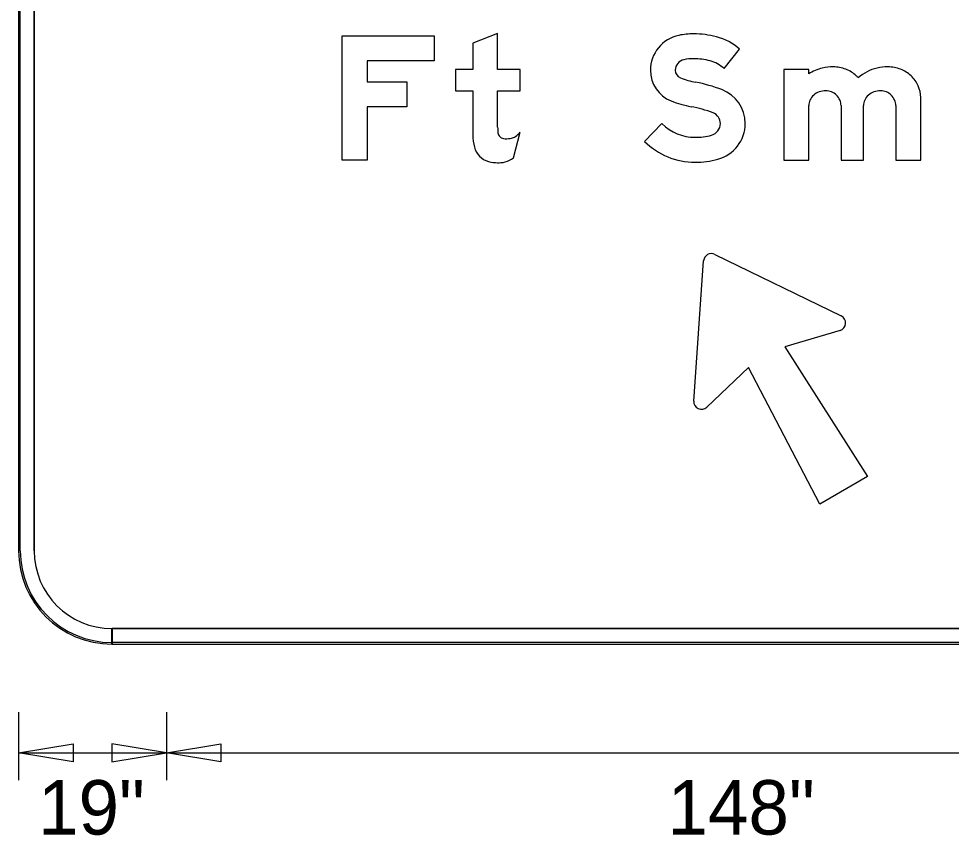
# Model space of a CAD drawing. Extents: x 2150010 to 2150174, y 145114 to 145224.
# Drawn here: x 2150031.52 to 2150041.52, y 145141.83 to 145150.58 of the extents above; entities that cross this region are included whole.
import ezdxf

# ---------------------------------------------------------------- set-up
doc = ezdxf.new("R2010")
doc.units = 0
for name, color, linetype in [('GSBWFILL', 7, 'Continuous'), ('GSCOLORFILL', 7, 'Continuous'), ('GSDIMS', 7, 'Continuous'), ('GSOUTLINE', 7, 'Continuous')]:
    doc.layers.add(name, color=color, linetype=linetype)

msp = doc.modelspace()

# ---------------------------------------------------------------- linework, layer by layer
at = {"layer": 'GSBWFILL'}
for p, q in [((2150031.52, 145156.8829), (2150031.52, 145144.8829)), ((2150031.6867, 145144.8829), (2150031.6867, 145156.8829)), ((2150036.8232, 145149.0925), (2150036.8934, 145149.3685)), ((2150032.52, 145143.8829), (2150032.52, 145144.0496)), ((2150046.02, 145144.0496), (2150032.5217, 145144.0496)), ((2150032.5217, 145144.0496), (2150032.5217, 145143.8829)), ((2150032.5217, 145143.8829), (2150046.02, 145143.8829))]:
    msp.add_line(p, q, dxfattribs=at)
for points in [[(2150036.6534, 145149.421), (2150036.6534, 145149.811), (2150036.8934, 145149.811), (2150036.8934, 145150.041), (2150036.6534, 145150.041), (2150036.6534, 145150.4243), (2150036.3867, 145150.3232), (2150036.3867, 145150.041), (2150036.2001, 145150.041), (2150036.2001, 145149.811), (2150036.3867, 145149.811), (2150036.3867, 145149.3404)], [(2150039.0801, 145150.0491), (2150039.245, 145150.2595)], [(2150039.9867, 145149.9928), (2150039.9867, 145150.041), (2150039.72, 145150.041), (2150039.72, 145149.0677), (2150039.9867, 145149.0677), (2150039.9867, 145149.6525)], [(2150040.92, 145149.6525), (2150040.92, 145149.0677), (2150041.1867, 145149.0677), (2150041.1867, 145149.7402)], [(2150040.3334, 145149.6525), (2150040.3334, 145149.0677), (2150040.5734, 145149.0677), (2150040.5734, 145149.6525)], [(2150038.4144, 145149.4595), (2150038.2267, 145149.2701)], [(2150038.9808, 145148.0592), (2150040.3351, 145147.3993)], [(2150038.7555, 145146.4873), (2150038.8611, 145147.9901)], [(2150040.3223, 145147.2444), (2150039.7313, 145147.0695), (2150040.6182, 145145.6777), (2150040.1048, 145145.3813), (2150039.343, 145146.8453), (2150038.896, 145146.4209)]]:
    msp.add_lwpolyline(points, dxfattribs=at)
msp.add_lwpolyline([(2150034.9867, 145150.401), (2150035.9734, 145150.401), (2150035.9734, 145150.1343), (2150035.2534, 145150.1343), (2150035.2534, 145149.9077), (2150035.6801, 145149.9077), (2150035.6801, 145149.641), (2150035.2534, 145149.641), (2150035.2534, 145149.0677), (2150034.9867, 145149.0677)], close=True, dxfattribs=at)
for centre, radius, start, end in [((2150038.9443, 145147.9842), 0.0834, 64.02227, 175.97773), ((2150040.2986, 145147.3243), 0.0834, 286.48453, 64.02227), ((2150038.8386, 145146.4814), 0.0834, 175.97773, 313.51547), ((2150032.52, 145144.8829), 1, 180, 270), ((2150032.52, 145144.8829), 0.8333, 180, 270)]:
    msp.add_arc(centre, radius, start, end, dxfattribs=at)
for centre, major_axis, ratio, start_param, end_param in [((2150038.7533, 145149.6365), (0, 0.7855), 0.999994, 0, 0.202758), ((2150038.7533, 145149.4588), (0, 0.9632), 0.999994, 6.026234, 6.283185), ((2150038.6721, 145150.0318), (0, 0.382), 0.999994, 0.202758, 1.570796), ((2150038.8427, 145149.799), (0, 0.6115), 0.999994, 5.565152, 6.026234), ((2150038.6721, 145150.0318), (0, 0.1153), 0.999994, 0.202758, 1.570796), ((2150038.7533, 145149.6365), (0, 0.5188), 0.999994, 0, 0.202758), ((2150038.7533, 145149.4588), (0, 0.6965), 0.999994, 6.026234, 6.283185), ((2150038.8427, 145149.799), (0, 0.3448), 0.999994, 5.523837, 6.026234), ((2150038.644, 145150.0318), (0, 0.3538), 0.999994, 1.570796, 2.761249), ((2150038.644, 145150.0318), (0, 0.0872), 0.999994, 1.570796, 2.761249), ((2150040.2447, 145149.5879), (0, 0.4802), 0.999997, 0.235088, 0.567132), ((2150040.2492, 145149.5343), (0, 0.5334), 0.999997, 0, 0.219986), ((2150040.2492, 145149.6923), (0, 0.3754), 0.999997, 5.914285, 6.283185), ((2150040.2582, 145149.7156), (0, 0.3503), 0.999997, 5.532258, 5.914285), ((2150040.8313, 145149.5879), (0, 0.4802), 0.999997, 0.235088, 0.712455), ((2150040.8359, 145149.5343), (0, 0.5334), 0.999997, 0, 0.219986), ((2150040.8359, 145149.6923), (0, 0.3754), 0.999997, 5.914285, 6.283185), ((2150040.8449, 145149.7156), (0, 0.3503), 0.999997, 5.532258, 5.914285), ((2150038.9345, 145150.7586), (0, 0.8699), 0.999994, 2.761249, 2.95744), ((2150040.2722, 145149.7306), (0, 0.3299), 0.999997, 5.44499, 5.532258), ((2150040.8589, 145149.7306), (0, 0.3299), 0.999997, 5.130076, 5.532258), ((2150038.478, 145148.3076), (0, 1.6233), 0.999994, 5.918637, 6.099033), ((2150038.9183, 145149.4612), (0, 0.3885), 0.999994, 4.712389, 5.918637), ((2150040.1696, 145149.6016), (0, 0.2099), 0.999997, 0, 0.345704), ((2150040.1696, 145149.6431), (0, 0.1684), 0.999997, 5.900624, 6.283185), ((2150040.7563, 145149.6016), (0, 0.2099), 0.999997, 0, 0.345704), ((2150040.7563, 145149.6431), (0, 0.1684), 0.999997, 5.900624, 6.283185), ((2150040.8805, 145149.7402), (0, 0.3062), 0.999997, 4.712389, 5.130076), ((2150040.1256, 145149.6525), (0, 0.1389), 0.999997, 1.126231, 1.570796), ((2150040.1469, 145149.6423), (0, 0.1625), 0.999997, 0.715718, 1.126231), ((2150040.1607, 145149.6265), (0, 0.1835), 0.999997, 0.345704, 0.715718), ((2150040.1715, 145149.6476), (0, 0.1635), 0.999997, 5.51227, 5.900624), ((2150040.1743, 145149.6506), (0, 0.1594), 0.999997, 5.115435, 5.51227), ((2150040.1787, 145149.6525), (0, 0.1546), 0.999997, 4.712389, 5.115435), ((2150040.7123, 145149.6525), (0, 0.1389), 0.999997, 1.126231, 1.570796), ((2150040.7336, 145149.6423), (0, 0.1625), 0.999997, 0.715718, 1.126231), ((2150040.7474, 145149.6265), (0, 0.1835), 0.999997, 0.345704, 0.715718), ((2150040.7581, 145149.6476), (0, 0.1635), 0.999997, 5.51227, 5.900624), ((2150040.761, 145149.6506), (0, 0.1594), 0.999997, 5.115435, 5.51227), ((2150040.7654, 145149.6525), (0, 0.1546), 0.999997, 4.712389, 5.115435), ((2150038.9345, 145150.7586), (0, 1.1366), 0.999994, 2.761249, 2.95744), ((2150038.478, 145148.3076), (0, 1.3566), 0.999994, 5.918637, 6.099033), ((2150038.9183, 145149.4612), (0, 0.1218), 0.999994, 4.712389, 5.918637), ((2150038.3227, 145149.421), (0, 1.6693), 0.999994, 1.570796, 1.606005), ((2150038.7696, 145149.8178), (0, 0.5044), 0.999994, 2.360607, 3.141593), ((2150038.9106, 145149.4612), (0, 0.1295), 0.999994, 3.401517, 4.712389), ((2150038.9106, 145149.4612), (0, 0.3961), 0.999994, 3.401517, 4.712389), ((2150036.9041, 145149.3404), (0, 0.5174), 0.999994, 1.570796, 1.830698), ((2150036.73, 145149.3752), (0, 0.0767), 0.999994, 1.74085, 2.407828), ((2150036.7324, 145149.3779), (0, 0.0803), 0.999994, 2.407828, 3.141593), ((2150036.7865, 145149.4022), (0, 0.1), 0.999994, 3.310762, 3.756278), ((2150036.7179, 145149.4994), (0, 0.2189), 0.999994, 3.756278, 4.071638), ((2150038.7696, 145149.9915), (0, 0.6782), 0.999994, 3.141593, 3.401517), ((2150036.7324, 145149.7187), (0, 0.4211), 0.999994, 3.141593, 3.310762), ((2150038.7696, 145149.8178), (0, 0.7711), 0.999994, 2.360607, 3.141593), ((2150036.6135, 145149.2631), (0, 0.2167), 0.999994, 1.830698, 2.869526), ((2150036.6534, 145149.4061), (0, 0.3651), 0.999994, 2.869526, 3.141593), ((2150036.6534, 145149.5669), (0, 0.5258), 0.999994, 3.141593, 3.205734), ((2150036.6732, 145149.2583), (0, 0.2167), 0.999994, 3.205734, 3.427755), ((2150036.6448, 145149.3548), (0, 0.3172), 0.999994, 3.427755, 3.738844), ((2150038.7696, 145149.9915), (0, 0.9449), 0.999994, 3.141593, 3.401517)]:
    msp.add_ellipse(centre, major_axis=major_axis, ratio=ratio, start_param=start_param, end_param=end_param, dxfattribs=at)
at = {"layer": 'GSCOLORFILL'}
for p, q in [((2150031.52, 145156.8829), (2150031.52, 145144.8829)), ((2150031.52, 145156.8829), (2150031.52, 145144.8829)), ((2150031.52, 145156.8829), (2150031.52, 145144.8829)), ((2150031.5367, 145144.8829), (2150031.5367, 145156.8829)), ((2150031.6867, 145144.8829), (2150031.6867, 145156.8829)), ((2150036.8232, 145149.0925), (2150036.8934, 145149.3685)), ((2150032.52, 145143.8829), (2150032.52, 145144.0496)), ((2150046.02, 145144.0496), (2150032.5217, 145144.0496)), ((2150032.5217, 145144.0496), (2150032.5217, 145143.8829)), ((2150032.52, 145143.8829), (2150032.52, 145143.8996)), ((2150032.52, 145143.8829), (2150046.02, 145143.8829)), ((2150046.02, 145143.8996), (2150032.5202, 145143.8996)), ((2150032.5202, 145143.8996), (2150032.5202, 145143.8829)), ((2150032.5202, 145143.8829), (2150046.02, 145143.8829)), ((2150032.5217, 145143.8829), (2150046.02, 145143.8829))]:
    msp.add_line(p, q, dxfattribs=at)
for points in [[(2150036.6534, 145149.421), (2150036.6534, 145149.811), (2150036.8934, 145149.811), (2150036.8934, 145150.041), (2150036.6534, 145150.041), (2150036.6534, 145150.4243), (2150036.3867, 145150.3232), (2150036.3867, 145150.041), (2150036.2001, 145150.041), (2150036.2001, 145149.811), (2150036.3867, 145149.811), (2150036.3867, 145149.3404)], [(2150039.0801, 145150.0491), (2150039.245, 145150.2595)], [(2150039.9867, 145149.9928), (2150039.9867, 145150.041), (2150039.72, 145150.041), (2150039.72, 145149.0677), (2150039.9867, 145149.0677), (2150039.9867, 145149.6525)], [(2150040.92, 145149.6525), (2150040.92, 145149.0677), (2150041.1867, 145149.0677), (2150041.1867, 145149.7402)], [(2150040.3334, 145149.6525), (2150040.3334, 145149.0677), (2150040.5734, 145149.0677), (2150040.5734, 145149.6525)], [(2150038.4144, 145149.4595), (2150038.2267, 145149.2701)], [(2150038.9808, 145148.0592), (2150040.3351, 145147.3993)], [(2150038.7555, 145146.4873), (2150038.8611, 145147.9901)], [(2150040.3223, 145147.2444), (2150039.7313, 145147.0695), (2150040.6182, 145145.6777), (2150040.1048, 145145.3813), (2150039.343, 145146.8453), (2150038.896, 145146.4209)]]:
    msp.add_lwpolyline(points, dxfattribs=at)
msp.add_lwpolyline([(2150034.9867, 145150.401), (2150035.9734, 145150.401), (2150035.9734, 145150.1343), (2150035.2534, 145150.1343), (2150035.2534, 145149.9077), (2150035.6801, 145149.9077), (2150035.6801, 145149.641), (2150035.2534, 145149.641), (2150035.2534, 145149.0677), (2150034.9867, 145149.0677)], close=True, dxfattribs=at)
for centre, radius, start, end in [((2150038.9443, 145147.9842), 0.0834, 64.02227, 175.97773), ((2150040.2986, 145147.3243), 0.0834, 286.48453, 64.02227), ((2150038.8386, 145146.4814), 0.0834, 175.97773, 313.51547), ((2150032.52, 145144.8829), 1, 180, 270), ((2150032.52, 145144.8829), 1, 180, 270), ((2150032.52, 145144.8829), 1, 180, 270), ((2150032.52, 145144.8829), 0.9833, 180, 270), ((2150032.52, 145144.8829), 0.8333, 180, 270)]:
    msp.add_arc(centre, radius, start, end, dxfattribs=at)
for centre, major_axis, ratio, start_param, end_param in [((2150038.7533, 145149.6365), (0, 0.7855), 0.999994, 0, 0.202758), ((2150038.7533, 145149.4588), (0, 0.9632), 0.999994, 6.026234, 6.283185), ((2150038.6721, 145150.0318), (0, 0.382), 0.999994, 0.202758, 1.570796), ((2150038.8427, 145149.799), (0, 0.6115), 0.999994, 5.565152, 6.026234), ((2150038.6721, 145150.0318), (0, 0.1153), 0.999994, 0.202758, 1.570796), ((2150038.7533, 145149.6365), (0, 0.5188), 0.999994, 0, 0.202758), ((2150038.7533, 145149.4588), (0, 0.6965), 0.999994, 6.026234, 6.283185), ((2150038.8427, 145149.799), (0, 0.3448), 0.999994, 5.523837, 6.026234), ((2150038.644, 145150.0318), (0, 0.3538), 0.999994, 1.570796, 2.761249), ((2150038.644, 145150.0318), (0, 0.0872), 0.999994, 1.570796, 2.761249), ((2150040.2447, 145149.5879), (0, 0.4802), 0.999997, 0.235088, 0.567132), ((2150040.2492, 145149.5343), (0, 0.5334), 0.999997, 0, 0.219986), ((2150040.2492, 145149.6923), (0, 0.3754), 0.999997, 5.914285, 6.283185), ((2150040.2582, 145149.7156), (0, 0.3503), 0.999997, 5.532258, 5.914285), ((2150040.8313, 145149.5879), (0, 0.4802), 0.999997, 0.235088, 0.712455), ((2150040.8359, 145149.5343), (0, 0.5334), 0.999997, 0, 0.219986), ((2150040.8359, 145149.6923), (0, 0.3754), 0.999997, 5.914285, 6.283185), ((2150040.8449, 145149.7156), (0, 0.3503), 0.999997, 5.532258, 5.914285), ((2150038.9345, 145150.7586), (0, 0.8699), 0.999994, 2.761249, 2.95744), ((2150040.2722, 145149.7306), (0, 0.3299), 0.999997, 5.44499, 5.532258), ((2150040.8589, 145149.7306), (0, 0.3299), 0.999997, 5.130076, 5.532258), ((2150038.478, 145148.3076), (0, 1.6233), 0.999994, 5.918637, 6.099033), ((2150038.9183, 145149.4612), (0, 0.3885), 0.999994, 4.712389, 5.918637), ((2150040.1696, 145149.6016), (0, 0.2099), 0.999997, 0, 0.345704), ((2150040.1696, 145149.6431), (0, 0.1684), 0.999997, 5.900624, 6.283185), ((2150040.7563, 145149.6016), (0, 0.2099), 0.999997, 0, 0.345704), ((2150040.7563, 145149.6431), (0, 0.1684), 0.999997, 5.900624, 6.283185), ((2150040.8805, 145149.7402), (0, 0.3062), 0.999997, 4.712389, 5.130076), ((2150040.1256, 145149.6525), (0, 0.1389), 0.999997, 1.126231, 1.570796), ((2150040.1469, 145149.6423), (0, 0.1625), 0.999997, 0.715718, 1.126231), ((2150040.1607, 145149.6265), (0, 0.1835), 0.999997, 0.345704, 0.715718), ((2150040.1715, 145149.6476), (0, 0.1635), 0.999997, 5.51227, 5.900624), ((2150040.1743, 145149.6506), (0, 0.1594), 0.999997, 5.115435, 5.51227), ((2150040.1787, 145149.6525), (0, 0.1546), 0.999997, 4.712389, 5.115435), ((2150040.7123, 145149.6525), (0, 0.1389), 0.999997, 1.126231, 1.570796), ((2150040.7336, 145149.6423), (0, 0.1625), 0.999997, 0.715718, 1.126231), ((2150040.7474, 145149.6265), (0, 0.1835), 0.999997, 0.345704, 0.715718), ((2150040.7581, 145149.6476), (0, 0.1635), 0.999997, 5.51227, 5.900624), ((2150040.761, 145149.6506), (0, 0.1594), 0.999997, 5.115435, 5.51227), ((2150040.7654, 145149.6525), (0, 0.1546), 0.999997, 4.712389, 5.115435), ((2150038.9345, 145150.7586), (0, 1.1366), 0.999994, 2.761249, 2.95744), ((2150038.478, 145148.3076), (0, 1.3566), 0.999994, 5.918637, 6.099033), ((2150038.9183, 145149.4612), (0, 0.1218), 0.999994, 4.712389, 5.918637), ((2150038.3227, 145149.421), (0, 1.6693), 0.999994, 1.570796, 1.606005), ((2150038.7696, 145149.8178), (0, 0.5044), 0.999994, 2.360607, 3.141593), ((2150038.9106, 145149.4612), (0, 0.1295), 0.999994, 3.401517, 4.712389), ((2150038.9106, 145149.4612), (0, 0.3961), 0.999994, 3.401517, 4.712389), ((2150036.9041, 145149.3404), (0, 0.5174), 0.999994, 1.570796, 1.830698), ((2150036.73, 145149.3752), (0, 0.0767), 0.999994, 1.74085, 2.407828), ((2150036.7324, 145149.3779), (0, 0.0803), 0.999994, 2.407828, 3.141593), ((2150036.7865, 145149.4022), (0, 0.1), 0.999994, 3.310762, 3.756278), ((2150036.7179, 145149.4994), (0, 0.2189), 0.999994, 3.756278, 4.071638), ((2150038.7696, 145149.9915), (0, 0.6782), 0.999994, 3.141593, 3.401517), ((2150036.7324, 145149.7187), (0, 0.4211), 0.999994, 3.141593, 3.310762), ((2150038.7696, 145149.8178), (0, 0.7711), 0.999994, 2.360607, 3.141593), ((2150036.6135, 145149.2631), (0, 0.2167), 0.999994, 1.830698, 2.869526), ((2150036.6534, 145149.4061), (0, 0.3651), 0.999994, 2.869526, 3.141593), ((2150036.6534, 145149.5669), (0, 0.5258), 0.999994, 3.141593, 3.205734), ((2150036.6732, 145149.2583), (0, 0.2167), 0.999994, 3.205734, 3.427755), ((2150036.6448, 145149.3548), (0, 0.3172), 0.999994, 3.427755, 3.738844), ((2150038.7696, 145149.9915), (0, 0.9449), 0.999994, 3.141593, 3.401517)]:
    msp.add_ellipse(centre, major_axis=major_axis, ratio=ratio, start_param=start_param, end_param=end_param, dxfattribs=at)
at = {"layer": 'GSDIMS'}
for p, q in [((2150031.52, 145143.1537), (2150031.52, 145142.4246)), ((2150031.52, 145143.1537), (2150031.52, 145142.4246)), ((2150033.1033, 145143.1537), (2150033.1033, 145142.4246)), ((2150033.1033, 145143.1537), (2150033.1033, 145142.4246)), ((2150031.52, 145142.7162), (2150033.1033, 145142.7162)), ((2150033.1033, 145142.7162), (2150045.4368, 145142.7162))]:
    msp.add_line(p, q, dxfattribs=at)
for points in [[(2150031.52, 145142.7162), (2150032.1033, 145142.8135), (2150032.1033, 145142.619)], [(2150033.1033, 145142.7162), (2150032.52, 145142.8135), (2150032.52, 145142.619)], [(2150033.1033, 145142.7162), (2150033.6866, 145142.8135), (2150033.6866, 145142.619)]]:
    msp.add_lwpolyline(points, close=True, dxfattribs=at)
at = {"layer": 'GSOUTLINE'}
for p, q in [((2150031.52, 145156.8829), (2150031.52, 145144.8829)), ((2150031.6867, 145156.8829), (2150031.6867, 145144.8829)), ((2150036.8232, 145149.0925), (2150036.8934, 145149.3685)), ((2150032.52, 145144.0496), (2150046.02, 145144.0496)), ((2150032.52, 145143.8829), (2150046.02, 145143.8829))]:
    msp.add_line(p, q, dxfattribs=at)
for points in [[(2150036.6534, 145149.421), (2150036.6534, 145149.811), (2150036.8934, 145149.811), (2150036.8934, 145150.041), (2150036.6534, 145150.041), (2150036.6534, 145150.4243), (2150036.3867, 145150.3232), (2150036.3867, 145150.041), (2150036.2001, 145150.041), (2150036.2001, 145149.811), (2150036.3867, 145149.811), (2150036.3867, 145149.3404)], [(2150039.0801, 145150.0491), (2150039.245, 145150.2595)], [(2150039.9867, 145149.9928), (2150039.9867, 145150.041), (2150039.72, 145150.041), (2150039.72, 145149.0677), (2150039.9867, 145149.0677), (2150039.9867, 145149.6525)], [(2150040.92, 145149.6525), (2150040.92, 145149.0677), (2150041.1867, 145149.0677), (2150041.1867, 145149.7402)], [(2150040.3334, 145149.6525), (2150040.3334, 145149.0677), (2150040.5734, 145149.0677), (2150040.5734, 145149.6525)], [(2150038.4144, 145149.4595), (2150038.2267, 145149.2701)], [(2150038.9808, 145148.0592), (2150040.3351, 145147.3993)], [(2150038.7555, 145146.4873), (2150038.8611, 145147.9901)], [(2150040.3223, 145147.2444), (2150039.7313, 145147.0695), (2150040.6182, 145145.6777), (2150040.1048, 145145.3813), (2150039.343, 145146.8453), (2150038.896, 145146.4209)]]:
    msp.add_lwpolyline(points, dxfattribs=at)
msp.add_lwpolyline([(2150034.9867, 145150.401), (2150035.9734, 145150.401), (2150035.9734, 145150.1343), (2150035.2534, 145150.1343), (2150035.2534, 145149.9077), (2150035.6801, 145149.9077), (2150035.6801, 145149.641), (2150035.2534, 145149.641), (2150035.2534, 145149.0677), (2150034.9867, 145149.0677)], close=True, dxfattribs=at)
for centre, radius, start, end in [((2150038.9443, 145147.9842), 0.0834, 64.02227, 175.97773), ((2150040.2986, 145147.3243), 0.0834, 286.48453, 64.02227), ((2150038.8386, 145146.4814), 0.0834, 175.97773, 313.51547), ((2150032.52, 145144.8829), 1, 180, 270), ((2150032.52, 145144.8829), 0.8333, 180, 270)]:
    msp.add_arc(centre, radius, start, end, dxfattribs=at)
for centre, major_axis, ratio, start_param, end_param in [((2150038.7533, 145149.6365), (0, 0.7855), 0.999994, 0, 0.202758), ((2150038.7533, 145149.4588), (0, 0.9632), 0.999994, 6.026234, 6.283185), ((2150038.6721, 145150.0318), (0, 0.382), 0.999994, 0.202758, 1.570796), ((2150038.8427, 145149.799), (0, 0.6115), 0.999994, 5.565152, 6.026234), ((2150038.6721, 145150.0318), (0, 0.1153), 0.999994, 0.202758, 1.570796), ((2150038.7533, 145149.6365), (0, 0.5188), 0.999994, 0, 0.202758), ((2150038.7533, 145149.4588), (0, 0.6965), 0.999994, 6.026234, 6.283185), ((2150038.8427, 145149.799), (0, 0.3448), 0.999994, 5.523837, 6.026234), ((2150038.644, 145150.0318), (0, 0.3538), 0.999994, 1.570796, 2.761249), ((2150038.644, 145150.0318), (0, 0.0872), 0.999994, 1.570796, 2.761249), ((2150040.2447, 145149.5879), (0, 0.4802), 0.999997, 0.235088, 0.567132), ((2150040.2492, 145149.5343), (0, 0.5334), 0.999997, 0, 0.219986), ((2150040.2492, 145149.6923), (0, 0.3754), 0.999997, 5.914285, 6.283185), ((2150040.2582, 145149.7156), (0, 0.3503), 0.999997, 5.532258, 5.914285), ((2150040.8313, 145149.5879), (0, 0.4802), 0.999997, 0.235088, 0.712455), ((2150040.8359, 145149.5343), (0, 0.5334), 0.999997, 0, 0.219986), ((2150040.8359, 145149.6923), (0, 0.3754), 0.999997, 5.914285, 6.283185), ((2150040.8449, 145149.7156), (0, 0.3503), 0.999997, 5.532258, 5.914285), ((2150038.9345, 145150.7586), (0, 0.8699), 0.999994, 2.761249, 2.95744), ((2150040.2722, 145149.7306), (0, 0.3299), 0.999997, 5.44499, 5.532258), ((2150040.8589, 145149.7306), (0, 0.3299), 0.999997, 5.130076, 5.532258), ((2150038.478, 145148.3076), (0, 1.6233), 0.999994, 5.918637, 6.099033), ((2150038.9183, 145149.4612), (0, 0.3885), 0.999994, 4.712389, 5.918637), ((2150040.1696, 145149.6016), (0, 0.2099), 0.999997, 0, 0.345704), ((2150040.1696, 145149.6431), (0, 0.1684), 0.999997, 5.900624, 6.283185), ((2150040.7563, 145149.6016), (0, 0.2099), 0.999997, 0, 0.345704), ((2150040.7563, 145149.6431), (0, 0.1684), 0.999997, 5.900624, 6.283185), ((2150040.8805, 145149.7402), (0, 0.3062), 0.999997, 4.712389, 5.130076), ((2150040.1256, 145149.6525), (0, 0.1389), 0.999997, 1.126231, 1.570796), ((2150040.1469, 145149.6423), (0, 0.1625), 0.999997, 0.715718, 1.126231), ((2150040.1607, 145149.6265), (0, 0.1835), 0.999997, 0.345704, 0.715718), ((2150040.1715, 145149.6476), (0, 0.1635), 0.999997, 5.51227, 5.900624), ((2150040.1743, 145149.6506), (0, 0.1594), 0.999997, 5.115435, 5.51227), ((2150040.1787, 145149.6525), (0, 0.1546), 0.999997, 4.712389, 5.115435), ((2150040.7123, 145149.6525), (0, 0.1389), 0.999997, 1.126231, 1.570796), ((2150040.7336, 145149.6423), (0, 0.1625), 0.999997, 0.715718, 1.126231), ((2150040.7474, 145149.6265), (0, 0.1835), 0.999997, 0.345704, 0.715718), ((2150040.7581, 145149.6476), (0, 0.1635), 0.999997, 5.51227, 5.900624), ((2150040.761, 145149.6506), (0, 0.1594), 0.999997, 5.115435, 5.51227), ((2150040.7654, 145149.6525), (0, 0.1546), 0.999997, 4.712389, 5.115435), ((2150038.9345, 145150.7586), (0, 1.1366), 0.999994, 2.761249, 2.95744), ((2150038.478, 145148.3076), (0, 1.3566), 0.999994, 5.918637, 6.099033), ((2150038.9183, 145149.4612), (0, 0.1218), 0.999994, 4.712389, 5.918637), ((2150038.3227, 145149.421), (0, 1.6693), 0.999994, 1.570796, 1.606005), ((2150038.7696, 145149.8178), (0, 0.5044), 0.999994, 2.360607, 3.141593), ((2150038.9106, 145149.4612), (0, 0.1295), 0.999994, 3.401517, 4.712389), ((2150038.9106, 145149.4612), (0, 0.3961), 0.999994, 3.401517, 4.712389), ((2150036.9041, 145149.3404), (0, 0.5174), 0.999994, 1.570796, 1.830698), ((2150036.73, 145149.3752), (0, 0.0767), 0.999994, 1.74085, 2.407828), ((2150036.7324, 145149.3779), (0, 0.0803), 0.999994, 2.407828, 3.141593), ((2150036.7865, 145149.4022), (0, 0.1), 0.999994, 3.310762, 3.756278), ((2150036.7179, 145149.4994), (0, 0.2189), 0.999994, 3.756278, 4.071638), ((2150038.7696, 145149.9915), (0, 0.6782), 0.999994, 3.141593, 3.401517), ((2150036.7324, 145149.7187), (0, 0.4211), 0.999994, 3.141593, 3.310762), ((2150038.7696, 145149.8178), (0, 0.7711), 0.999994, 2.360607, 3.141593), ((2150036.6135, 145149.2631), (0, 0.2167), 0.999994, 1.830698, 2.869526), ((2150036.6534, 145149.4061), (0, 0.3651), 0.999994, 2.869526, 3.141593), ((2150036.6534, 145149.5669), (0, 0.5258), 0.999994, 3.141593, 3.205734), ((2150036.6732, 145149.2583), (0, 0.2167), 0.999994, 3.205734, 3.427755), ((2150036.6448, 145149.3548), (0, 0.3172), 0.999994, 3.427755, 3.738844), ((2150038.7696, 145149.9915), (0, 0.9449), 0.999994, 3.141593, 3.401517)]:
    msp.add_ellipse(centre, major_axis=major_axis, ratio=ratio, start_param=start_param, end_param=end_param, dxfattribs=at)

# ---------------------------------------------------------------- texts
at = {"layer": 'GSDIMS'}
for s, p in [('19"', (2150031.7278, 145141.8412)), ('148"', (2150038.4738, 145141.8412))]:
    msp.add_text(s, height=0.58333, dxfattribs=at).set_placement(p)

doc.saveas('drawing.dxf')
